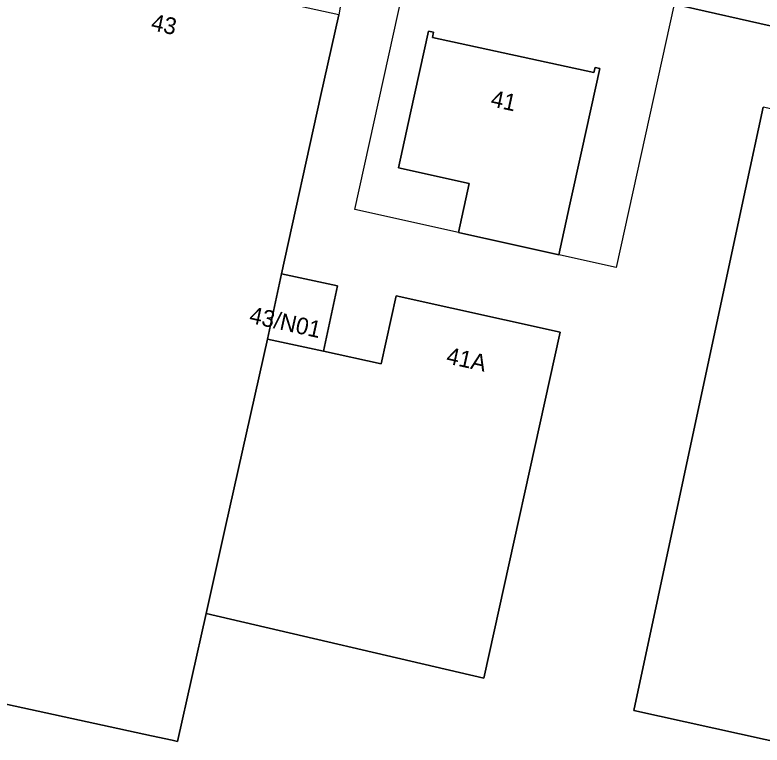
# Model space of a CAD drawing. Extents: x 162172 to 163187, y 382874 to 383685.
# Drawn here: x 162616.09 to 162660.71, y 383101.71 to 383145.3 of the extents above; entities that cross this region are included whole.
import ezdxf

# ---------------------------------------------------------------- set-up
doc = ezdxf.new("R2010")
doc.units = 0
for name, color, linetype in [('IMGEO_Erf', 7, 'Continuous'), ('IMGEO_Hek', 7, 'Continuous'), ('IMGEO_Pand', 7, 'Continuous'), ('IMGEO_Pand_nummerreeks', 7, 'Continuous'), ('IMGEO_Voetpad_open', 7, 'Continuous')]:
    doc.layers.add(name, color=color, linetype=linetype)

msp = doc.modelspace()

# ---------------------------------------------------------------- linework, layer by layer
at = {"layer": 'IMGEO_Erf'}
for points in [[(162661.814, 383144.51), (162655.461, 383145.939), (162651.832, 383146.756), (162641.258, 383149.088), (162639.859, 383149.393), (162636.279, 383150.172), (162635.424, 383145.306), (162634.345, 383140.424), (162632.005, 383129.841), (162635.351, 383129.123), (162634.513, 383125.217), (162637.959, 383124.478), (162638.85, 383128.535), (162648.655, 383126.367), (162644.086, 383105.708), (162627.504, 383109.562), (162625.79, 383101.932), (162625.476, 383102), (162624.255, 383102.266), (162605.924, 383106.249)], [(162670.276, 383099.967), (162653.057, 383103.778), (162657.479, 383124.416), (162659.724, 383134.895), (162660.771, 383139.784)]]:
    msp.add_lwpolyline(points, dxfattribs=at)
msp.add_lwpolyline([(162642.576, 383132.31), (162643.223, 383135.236), (162638.994, 383136.171), (162639.715, 383139.449), (162640.788, 383144.332), (162641.091, 383144.266), (162641.023, 383143.954), (162650.666, 383141.852), (162650.734, 383142.164), (162651.027, 383142.1), (162649.949, 383137.218), (162649.218, 383133.91), (162648.572, 383130.984)], close=True, dxfattribs=at)
at = {"layer": 'IMGEO_Hek'}
msp.add_lwpolyline([(162655.461, 383145.939), (162651.986, 383130.225), (162636.383, 383133.676), (162639.859, 383149.393)], dxfattribs=at)
at = {"layer": 'IMGEO_Pand'}
for points in [[(162631.181, 383125.935), (162632.005, 383129.841), (162634.345, 383140.424), (162635.424, 383145.306), (162615.917, 383149.56), (162609.336, 383120.209), (162609.038, 383120.276), (162607.662, 383113.818), (162605.924, 383106.249), (162624.255, 383102.266), (162625.476, 383102), (162625.79, 383101.932), (162627.504, 383109.562), (162628.67, 383114.755)], [(162651.027, 383142.1), (162650.734, 383142.164), (162650.666, 383141.852), (162641.023, 383143.954), (162641.091, 383144.266), (162640.788, 383144.332), (162639.715, 383139.449), (162638.994, 383136.171), (162643.223, 383135.236), (162642.576, 383132.31), (162648.572, 383130.984), (162649.218, 383133.91), (162649.949, 383137.218)], [(162659.724, 383134.895), (162657.479, 383124.416), (162653.057, 383103.778), (162670.276, 383099.967), (162678.076, 383135.965), (162660.771, 383139.784)], [(162632.005, 383129.841), (162631.181, 383125.935), (162634.513, 383125.217), (162635.351, 383129.123)], [(162648.655, 383126.367), (162638.85, 383128.535), (162637.959, 383124.478), (162634.513, 383125.217), (162631.181, 383125.935), (162628.67, 383114.755), (162627.504, 383109.562), (162644.086, 383105.708)]]:
    msp.add_lwpolyline(points, close=True, dxfattribs=at)
at = {"layer": 'IMGEO_Voetpad_open'}
msp.add_lwpolyline([(162661.814, 383144.51), (162663.396, 383144.154), (162664.161, 383147.688), (162652.581, 383150.202), (162651.832, 383146.756), (162655.461, 383145.939)], close=True, dxfattribs=at)

# ---------------------------------------------------------------- texts
at = {"layer": 'IMGEO_Pand_nummerreeks'}
for s, rotation, p in [('43', 347.6986, (162624.165, 383144.404)), ('41', 347.7043, (162644.449, 383139.85)), ('43/N01', 347.55, (162630.031, 383126.928)), ('41A', 347.5554, (162641.798, 383124.507))]:
    msp.add_text(s, height=1, rotation=rotation, dxfattribs=at).set_placement(p)

doc.saveas('drawing.dxf')
